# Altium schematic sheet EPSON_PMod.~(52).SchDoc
size A4
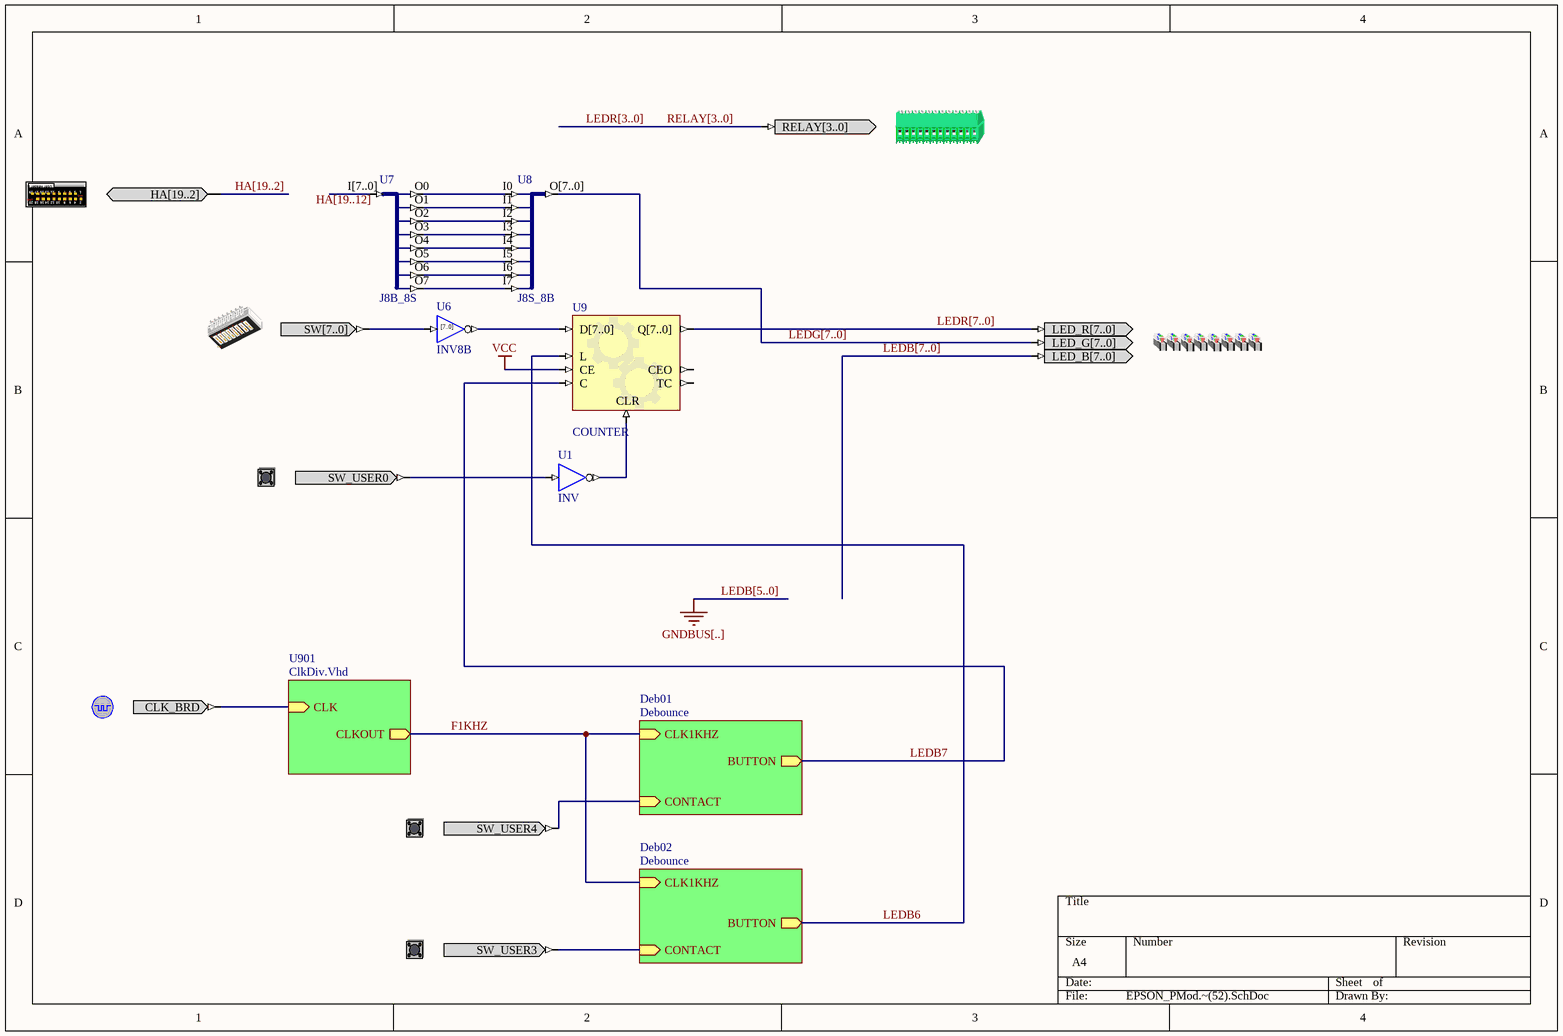
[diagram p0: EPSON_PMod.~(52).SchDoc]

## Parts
(Parts that share a designator on the sheet are numbered #1, #2 ... from top to bottom, then left to right.)
?#1  RELAYCNTR  (value not drawn)
?#2  USER_HEADER_A  (value not drawn)
?#3  DIPSWITCH  (value not drawn)
?#4  LEDS_RGB  (value not drawn)
?#5  USER_BUTTON0  (value not drawn)
?#6  CLOCK_BOARD  (value not drawn)
?#7  USER_BUTTON4  (value not drawn)
?#8  USER_BUTTON3  (value not drawn)
U1  INV
U6  INV8B
U7  J8B_8S
U8  J8S_8B
U9  COUNTER

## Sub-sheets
Deb01 = Debounce: CONTACT (in), BUTTON (out), CLK1KHZ (in)
Deb02 = Debounce: CONTACT (in), BUTTON (out), CLK1KHZ (in)
U901 = ClkDiv.Vhd: CLK (in), CLKOUT (out)

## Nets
VCC: U9.CE
F1KHZ: sheet U901/CLKOUT, sheet Deb01/CLK1KHZ, sheet Deb02/CLK1KHZ
LEDB6: U9.L ; sheet Deb02/BUTTON
LEDB7: U9.C ; sheet Deb01/BUTTON
Net?#5_SW_USER0: ?#5.SW_USER0 U1.I
Net?#6_CLK_BRD: ?#6.CLK_BRD ; sheet U901/CLK
Net?#7_SW_USER4: ?#7.SW_USER4 ; sheet Deb01/CONTACT
Net?#8_SW_USER3: ?#8.SW_USER3 ; sheet Deb02/CONTACT
NetU1_O: U1.O U9.CLR
NetU7_O0: U7.O0 U8.I0
NetU7_O1: U7.O1 U8.I1
NetU7_O2: U7.O2 U8.I2
NetU7_O3: U7.O3 U8.I3
NetU7_O4: U7.O4 U8.I4
NetU7_O5: U7.O5 U8.I5
NetU7_O6: U7.O6 U8.I6
NetU7_O7: U7.O7 U8.I7

Not connected (* = marked no-connect by the designer): ?#1 RELAY[3..0]; ?#2 HA[19..2]; ?#3 SW[7..0]; ?#4 LED_B[7..0] LED_G[7..0] LED_R[7..0]; U6 I[7..0] O[7..0]; U7 I[7..0]; U8 O[7..0]; U9 CEO D[7..0] Q[7..0] TC

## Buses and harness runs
bus HA[19..2]
bus HA[19..12]
bus LEDB[5..0]
bus LEDB[7..0]
bus LEDG[7..0]
bus LEDR[3..0] = RELAY[3..0]
bus LEDR[7..0]

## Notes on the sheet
- Labels drawn without touching a wire or pin: GNDBUS[..], HA[19..12]

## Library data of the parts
?#1 = RELAYCNTR: RELAY; PortComponent: True
?#2 = USER_HEADER_A: User Header A; PortComponent: True
?#3 = DIPSWITCH: 8-Way Dip-Switch; PortComponent: True
?#4 = LEDS_RGB: LEDS RGB; PortComponent: True
?#5 = USER_BUTTON0: Generic User Button; PortComponent: True
?#6 = CLOCK_BOARD: Global System Clock Supply; PortComponent: True
?#7 = USER_BUTTON4: Generic User Button; PortComponent: True
?#8 = USER_BUTTON3: Generic User Button; PortComponent: True
U1 = INV: Inverter; FunctionalClass: Logic Primitive; ArchiveName: GENERIC; VHDLIB_SIM: GENERIC_LIB
U6 = INV8B: 8-Bit Inverter, Bus Version; XilinxEquivalent: INV8; FunctionalClass: Logic Primitive; SubClass: INV; PortSize: 8; ArchiveName: GENERIC; VHDLIB_SIM: GENERIC_LIB
U7 = J8B_8S: 8-Bit input bus to 8 single pin outputs; FunctionalClass: Bus Joiner; PortSize: 8; ArchiveName: GENERIC; VHDLIB_SIM: GENERIC_LIB
U8 = J8S_8B: 8 Single pin inputs to single 8-Bit output bus; FunctionalClass: Bus Joiner; PortSize: 8; ArchiveName: GENERIC; VHDLIB_SIM: GENERIC_LIB
U9 = COUNTER: Configurable Counter; ConfiguratorName: GENERIC_COUNTER; ConfigurationParameters: {}Version[1.0]{}Type[Binary]{}SyncReset[False]{}NegativeClockEdge[False]{}FixedDirection[True]{}IsIncrement[True]{}SignalWidth[8]{}MaxValue[255]{}BusOutput[True]{}Loadable[True]{}BusInput[True]{}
